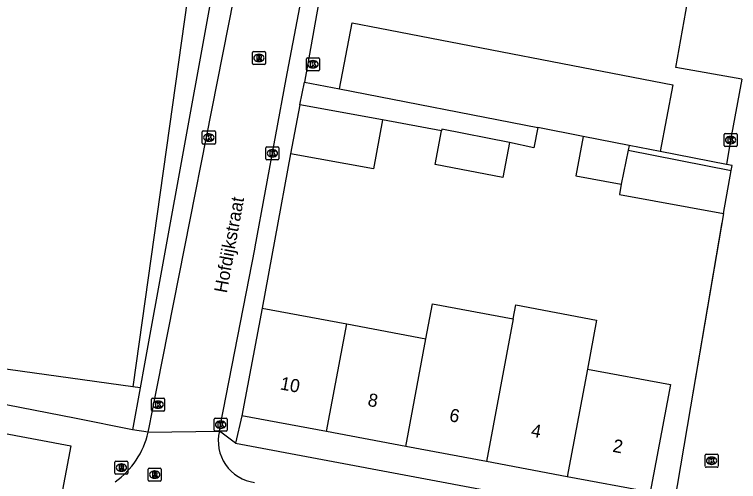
# Model space of a CAD drawing. Extents: x 161402 to 161933, y 381650 to 382313.
# Drawn here: x 161806.7 to 161862.2, y 381952.6 to 381988.4 of the extents above; entities that cross this region are included whole.
import ezdxf

# ---------------------------------------------------------------- set-up
doc = ezdxf.new("R2010")
doc.units = 0
for name, color, linetype in [('IMGEO_Groenvoorziening', 7, 'Continuous'), ('IMGEO_Kolk', 7, 'Continuous'), ('IMGEO_Muur', 7, 'Continuous'), ('IMGEO_Openbare_ruimte_label', 7, 'Continuous'), ('IMGEO_Pand', 7, 'Continuous'), ('IMGEO_Pand_nummerreeks', 7, 'Continuous'), ('IMGEO_Parkeervlak_gesloten', 7, 'Continuous'), ('IMGEO_Rijbaan_lokaal_gesloten', 7, 'Continuous'), ('IMGEO_Rijbaan_lokaal_open', 7, 'Continuous'), ('IMGEO_Rioolput', 7, 'Continuous'), ('IMGEO_Voetpad_open', 7, 'Continuous')]:
    doc.layers.add(name, color=color, linetype=linetype)

msp = doc.modelspace()

# ---------------------------------------------------------------- linework, layer by layer
at = {"layer": 'IMGEO_Groenvoorziening'}
for points in [[(161829.439, 382055.781), (161829.294, 382055.793), (161815.795, 381959.903)], [(161815.795, 381959.903), (161781.596, 381964.647)], [(161816.367, 381959.82), (161815.795, 381959.903)]]:
    msp.add_lwpolyline(points, dxfattribs=at)
at = {"layer": 'IMGEO_Kolk'}
for p, q in [((161829.118, 381984.183), (161829.118, 381985.035)), ((161829.193, 381985.109), (161830.045, 381985.109)), ((161830.119, 381985.035), (161830.119, 381984.183)), ((161829.606, 381984.889), (161829.631, 381984.889)), ((161830.045, 381984.109), (161829.193, 381984.109)), ((161829.629, 381984.329), (161829.604, 381984.329)), ((161821.209, 381979.497), (161822.061, 381979.497)), ((161821.134, 381978.571), (161821.134, 381979.423)), ((161821.622, 381979.277), (161821.647, 381979.277)), ((161822.135, 381979.423), (161822.135, 381978.571)), ((161861.134, 381978.379), (161861.134, 381979.231)), ((161861.209, 381979.305), (161862.061, 381979.305)), ((161861.622, 381979.085), (161861.647, 381979.085)), ((161862.135, 381979.231), (161862.135, 381978.379)), ((161822.061, 381978.497), (161821.209, 381978.497)), ((161821.645, 381978.717), (161821.62, 381978.717)), ((161861.645, 381978.525), (161861.62, 381978.525)), ((161826.008, 381977.362), (161826.008, 381978.214)), ((161826.083, 381978.288), (161826.935, 381978.288)), ((161826.496, 381978.068), (161826.521, 381978.068)), ((161827.009, 381978.214), (161827.009, 381977.362)), ((161862.061, 381978.305), (161861.209, 381978.305)), ((161826.935, 381977.288), (161826.083, 381977.288)), ((161826.519, 381977.508), (161826.494, 381977.508)), ((161817.244, 381958.104), (161817.244, 381958.956)), ((161817.319, 381959.03), (161818.171, 381959.03)), ((161818.245, 381958.956), (161818.245, 381958.104)), ((161817.732, 381958.81), (161817.757, 381958.81)), ((161818.171, 381958.03), (161817.319, 381958.03)), ((161817.755, 381958.25), (161817.73, 381958.25)), ((161822.039, 381956.565), (161822.039, 381957.417)), ((161822.114, 381957.491), (161822.966, 381957.491)), ((161822.527, 381957.271), (161822.552, 381957.271)), ((161823.04, 381957.417), (161823.04, 381956.565)), ((161822.55, 381956.711), (161822.525, 381956.711)), ((161822.966, 381956.491), (161822.114, 381956.491)), ((161859.677, 381953.805), (161859.677, 381954.657)), ((161859.752, 381954.731), (161860.604, 381954.731)), ((161860.165, 381954.511), (161860.19, 381954.511)), ((161860.678, 381954.657), (161860.678, 381953.805)), ((161860.188, 381953.951), (161860.163, 381953.951)), ((161860.604, 381953.731), (161859.752, 381953.731))]:
    msp.add_line(p, q, dxfattribs=at)
for points in [[(161829.118, 381984.183), (161829.118, 381985.035)], [(161829.193, 381985.109), (161830.045, 381985.109)], [(161830.119, 381985.035), (161830.119, 381984.183)], [(161829.439, 381984.809), (161829.562, 381984.809), (161829.562, 381984.658), (161829.692, 381984.809), (161829.856, 381984.809), (161829.71, 381984.658), (161829.863, 381984.409), (161829.711, 381984.409), (161829.626, 381984.573), (161829.562, 381984.506), (161829.562, 381984.409), (161829.439, 381984.409), (161829.439, 381984.809)], [(161830.045, 381984.109), (161829.193, 381984.109)], [(161821.209, 381979.497), (161822.061, 381979.497)], [(161821.134, 381978.571), (161821.134, 381979.423)], [(161821.455, 381979.197), (161821.578, 381979.197), (161821.578, 381979.046), (161821.708, 381979.197), (161821.872, 381979.197), (161821.726, 381979.046), (161821.879, 381978.797), (161821.727, 381978.797), (161821.642, 381978.961), (161821.578, 381978.894), (161821.578, 381978.797), (161821.455, 381978.797), (161821.455, 381979.197)], [(161822.135, 381979.423), (161822.135, 381978.571)], [(161861.134, 381978.379), (161861.134, 381979.231)], [(161861.209, 381979.305), (161862.061, 381979.305)], [(161861.455, 381979.005), (161861.578, 381979.005), (161861.578, 381978.854), (161861.708, 381979.005), (161861.872, 381979.005), (161861.726, 381978.854), (161861.879, 381978.605), (161861.727, 381978.605), (161861.642, 381978.769), (161861.578, 381978.702), (161861.578, 381978.605), (161861.455, 381978.605), (161861.455, 381979.005)], [(161862.135, 381979.231), (161862.135, 381978.379)], [(161822.061, 381978.497), (161821.209, 381978.497)], [(161826.008, 381977.362), (161826.008, 381978.214)], [(161826.083, 381978.288), (161826.935, 381978.288)], [(161826.329, 381977.988), (161826.452, 381977.988), (161826.452, 381977.837), (161826.582, 381977.988), (161826.746, 381977.988), (161826.6, 381977.837), (161826.753, 381977.588), (161826.601, 381977.588), (161826.516, 381977.752), (161826.452, 381977.685), (161826.452, 381977.588), (161826.329, 381977.588), (161826.329, 381977.988)], [(161827.009, 381978.214), (161827.009, 381977.362)], [(161862.061, 381978.305), (161861.209, 381978.305)], [(161826.935, 381977.288), (161826.083, 381977.288)], [(161817.244, 381958.104), (161817.244, 381958.956)], [(161817.319, 381959.03), (161818.171, 381959.03)], [(161818.245, 381958.956), (161818.245, 381958.104)], [(161817.565, 381958.73), (161817.688, 381958.73), (161817.688, 381958.579), (161817.818, 381958.73), (161817.982, 381958.73), (161817.836, 381958.579), (161817.989, 381958.33), (161817.837, 381958.33), (161817.752, 381958.494), (161817.688, 381958.427), (161817.688, 381958.33), (161817.565, 381958.33), (161817.565, 381958.73)], [(161818.171, 381958.03), (161817.319, 381958.03)], [(161822.039, 381956.565), (161822.039, 381957.417)], [(161822.114, 381957.491), (161822.966, 381957.491)], [(161823.04, 381957.417), (161823.04, 381956.565)], [(161822.36, 381957.191), (161822.483, 381957.191), (161822.483, 381957.04), (161822.613, 381957.191), (161822.777, 381957.191), (161822.631, 381957.04), (161822.784, 381956.791), (161822.632, 381956.791), (161822.547, 381956.955), (161822.483, 381956.888), (161822.483, 381956.791), (161822.36, 381956.791), (161822.36, 381957.191)], [(161822.966, 381956.491), (161822.114, 381956.491)], [(161859.677, 381953.805), (161859.677, 381954.657)], [(161859.752, 381954.731), (161860.604, 381954.731)], [(161860.678, 381954.657), (161860.678, 381953.805)], [(161859.998, 381954.431), (161860.121, 381954.431), (161860.121, 381954.28), (161860.251, 381954.431), (161860.415, 381954.431), (161860.269, 381954.28), (161860.422, 381954.031), (161860.27, 381954.031), (161860.185, 381954.195), (161860.121, 381954.128), (161860.121, 381954.031), (161859.998, 381954.031), (161859.998, 381954.431)], [(161860.604, 381953.731), (161859.752, 381953.731)]]:
    msp.add_lwpolyline(points, dxfattribs=at)
for centre, start, end in [((161829.195, 381985.033), 91.552, 178.448), ((161829.195, 381985.033), 91.552, 178.448), ((161830.043, 381985.033), 1.552, 88.448), ((161830.043, 381985.033), 1.552, 88.448), ((161829.195, 381984.185), 181.552, 268.448), ((161829.195, 381984.185), 181.552, 268.448), ((161830.043, 381984.185), 271.552, 358.448), ((161830.043, 381984.185), 271.552, 358.448), ((161821.211, 381979.421), 91.552, 178.448), ((161821.211, 381979.421), 91.552, 178.448), ((161822.059, 381979.421), 1.552, 88.448), ((161822.059, 381979.421), 1.552, 88.448), ((161861.211, 381979.229), 91.552, 178.448), ((161861.211, 381979.229), 91.552, 178.448), ((161862.059, 381979.229), 1.552, 88.448), ((161862.059, 381979.229), 1.552, 88.448), ((161821.211, 381978.573), 181.552, 268.448), ((161821.211, 381978.573), 181.552, 268.448), ((161822.059, 381978.573), 271.552, 358.448), ((161822.059, 381978.573), 271.552, 358.448), ((161861.211, 381978.381), 181.552, 268.448), ((161861.211, 381978.381), 181.552, 268.448), ((161862.059, 381978.381), 271.552, 358.448), ((161862.059, 381978.381), 271.552, 358.448), ((161826.085, 381978.212), 91.552, 178.448), ((161826.085, 381978.212), 91.552, 178.448), ((161826.933, 381978.212), 1.552, 88.448), ((161826.933, 381978.212), 1.552, 88.448), ((161826.085, 381977.364), 181.552, 268.448), ((161826.085, 381977.364), 181.552, 268.448), ((161826.933, 381977.364), 271.552, 358.448), ((161826.933, 381977.364), 271.552, 358.448), ((161817.321, 381958.954), 91.552, 178.448), ((161817.321, 381958.954), 91.552, 178.448), ((161818.169, 381958.954), 1.552, 88.448), ((161818.169, 381958.954), 1.552, 88.448), ((161817.321, 381958.106), 181.552, 268.448), ((161817.321, 381958.106), 181.552, 268.448), ((161818.169, 381958.106), 271.552, 358.448), ((161818.169, 381958.106), 271.552, 358.448), ((161822.116, 381957.415), 91.552, 178.448), ((161822.116, 381957.415), 91.552, 178.448), ((161822.964, 381957.415), 1.552, 88.448), ((161822.964, 381957.415), 1.552, 88.448), ((161822.116, 381956.567), 181.552, 268.448), ((161822.116, 381956.567), 181.552, 268.448), ((161822.964, 381956.567), 271.552, 358.448), ((161822.964, 381956.567), 271.552, 358.448), ((161859.754, 381954.655), 91.552, 178.448), ((161859.754, 381954.655), 91.552, 178.448), ((161860.602, 381954.655), 1.552, 88.448), ((161860.602, 381954.655), 1.552, 88.448), ((161859.754, 381953.807), 181.552, 268.448), ((161859.754, 381953.807), 181.552, 268.448), ((161860.602, 381953.807), 271.552, 358.448), ((161860.602, 381953.807), 271.552, 358.448)]:
    msp.add_arc(centre, 0.0765, start, end, dxfattribs=at)
for centre, major_axis, ratio, start_param, end_param in [((161829.605, 381984.609), (-0.387, 0.002), 0.722429, 4.712389, 7.853982), ((161829.63, 381984.609), (-0.39, 0.002), 0.717154, 1.570796, 4.712389), ((161821.621, 381978.997), (-0.387, 0.002), 0.722429, 4.712389, 7.853982), ((161821.646, 381978.997), (-0.39, 0.002), 0.717154, 1.570796, 4.712389), ((161861.621, 381978.805), (-0.387, 0.002), 0.722429, 4.712389, 7.853982), ((161861.646, 381978.805), (-0.39, 0.002), 0.717154, 1.570796, 4.712389), ((161826.495, 381977.788), (-0.387, 0.002), 0.722429, 4.712389, 7.853982), ((161826.52, 381977.788), (-0.39, 0.002), 0.717154, 1.570796, 4.712389), ((161817.731, 381958.53), (-0.387, 0.002), 0.722429, 4.712389, 7.853982), ((161817.756, 381958.53), (-0.39, 0.002), 0.717154, 1.570796, 4.712389), ((161822.526, 381956.991), (-0.387, 0.002), 0.722429, 4.712389, 7.853982), ((161822.551, 381956.991), (-0.39, 0.002), 0.717154, 1.570796, 4.712389), ((161860.164, 381954.231), (-0.387, 0.002), 0.722429, 4.712389, 7.853982), ((161860.189, 381954.231), (-0.39, 0.002), 0.717154, 1.570796, 4.712389)]:
    msp.add_ellipse(centre, major_axis=major_axis, ratio=ratio, start_param=start_param, end_param=end_param, dxfattribs=at)
at = {"layer": 'IMGEO_Muur'}
for points in [[(161827.883, 381977.756), (161826.684, 381971.203)], [(161860.954, 381972.49), (161858.562, 381958.352)], [(161826.684, 381971.203), (161825.719, 381965.932)]]:
    msp.add_lwpolyline(points, dxfattribs=at)
at = {"layer": 'IMGEO_Pand'}
for points in [[(161828.609, 381981.506), (161827.883, 381977.756)], [(161834.946, 381980.346), (161828.609, 381981.506)], [(161834.946, 381980.346), (161834.257, 381976.588), (161827.883, 381977.756)], [(161844.674, 381978.618), (161844.181, 381975.929), (161838.994, 381976.939), (161839.466, 381979.518)], [(161844.674, 381978.618), (161839.486, 381979.628), (161839.466, 381979.518)], [(161850.336, 381979.079), (161849.782, 381976.057), (161853.257, 381975.42)], [(161853.869, 381978.391), (161850.336, 381979.079)], [(161853.869, 381978.391), (161853.792, 381978.018)], [(161853.792, 381978.018), (161853.257, 381975.42)], [(161853.792, 381978.018), (161861.686, 381976.481)], [(161861.08, 381973.179), (161861.686, 381976.481)], [(161853.257, 381975.42), (161853.114, 381974.64), (161861.08, 381973.179)], [(161838.276, 381963.578), (161838.779, 381966.265), (161844.971, 381965.105)], [(161844.971, 381965.105), (161845.171, 381966.173), (161851.364, 381965.012), (161850.66, 381961.257)], [(161825.719, 381965.932), (161824.173, 381957.682)], [(161825.719, 381965.932), (161832.204, 381964.716)], [(161844.971, 381965.105), (161842.923, 381954.168)], [(161830.659, 381956.466), (161832.204, 381964.716)], [(161832.204, 381964.716), (161838.276, 381963.578)], [(161836.731, 381955.328), (161838.276, 381963.578)], [(161850.66, 381961.257), (161857.027, 381960.063), (161855.481, 381951.814), (161849.115, 381953.007)], [(161850.66, 381961.257), (161849.115, 381953.007)], [(161830.659, 381956.466), (161824.173, 381957.682)], [(161836.731, 381955.328), (161830.659, 381956.466)], [(161842.923, 381954.168), (161836.731, 381955.328)], [(161849.115, 381953.007), (161842.923, 381954.168)]]:
    msp.add_lwpolyline(points, dxfattribs=at)
at = {"layer": 'IMGEO_Parkeervlak_gesloten'}
for points in [[(161850.336, 381979.079), (161846.863, 381979.756)], [(161856.229, 381977.931), (161853.869, 381978.391)]]:
    msp.add_lwpolyline(points, dxfattribs=at)
at = {"layer": 'IMGEO_Rijbaan_lokaal_gesloten'}
for points in [[(161862.491, 381983.458), (161857.448, 381984.357), (161864.341, 382023.003)], [(161830.987, 381994.574), (161828.968, 381983.243)], [(161831.646, 381982.721), (161832.631, 381987.778), (161834.75, 381987.369), (161857.213, 381983.04), (161856.229, 381977.931)], [(161862.491, 381983.458), (161861.636, 381978.805), (161861.321, 381976.94)], [(161828.968, 381983.243), (161831.646, 381982.721)], [(161861.321, 381976.94), (161856.229, 381977.931)]]:
    msp.add_lwpolyline(points, dxfattribs=at)
at = {"layer": 'IMGEO_Rijbaan_lokaal_open'}
for points in [[(161822.45, 381956.505), (161822.54, 381956.991), (161825.164, 381970.44), (161825.196, 381970.616), (161827.554, 381983.498), (161830.695, 382000), (161833.899, 382016.966), (161836.784, 382033.46), (161839.275, 382047.946), (161841.729, 382061.924), (161844.797, 382079.199), (161847.522, 382094.137), (161855.583, 382102.928), (161859.869, 382107.508)], [(161816.977, 381956.412), (161817.094, 381956.896), (161817.254, 381957.834), (161824.386, 381993.913), (161825.157, 381998.089), (161825.499, 382000), (161827.39, 382010.57), (161829.195, 382020.232), (161830.73, 382029.273), (161834.543, 382050.384), (161834.774, 382051.699)], [(161832.505, 382048.322), (161822.827, 381995.34), (161816.701, 381961.668), (161816.367, 381959.82)], [(161828.609, 381981.506), (161828.968, 381983.243)], [(161827.883, 381977.756), (161826.684, 381971.203), (161825.719, 381965.932)], [(161861.686, 381976.481), (161861.755, 381976.855), (161861.321, 381976.94)], [(161861.08, 381973.179), (161858.562, 381958.352), (161857.033, 381949.323)], [(161816.367, 381959.82), (161815.783, 381956.589)], [(161824.173, 381957.682), (161823.681, 381955.575)], [(161816.977, 381956.412), (161815.783, 381956.589)], [(161816.977, 381956.412), (161822.45, 381956.505)], [(161823.681, 381955.575), (161822.45, 381956.505)]]:
    msp.add_lwpolyline(points, dxfattribs=at)
for centre, radius, start, end in [((161810.822, 381957.769), 6.303, 305.142, 347.5685), ((161825.556, 381955.744), 3.198, 166.2409, 262.5929)]:
    msp.add_arc(centre, radius, start, end, dxfattribs=at)
at = {"layer": 'IMGEO_Rioolput'}
for p, q in [((161825.047, 381985.592), (161825.899, 381985.592)), ((161824.972, 381984.666), (161824.972, 381985.518)), ((161825.46, 381985.372), (161825.485, 381985.372)), ((161825.973, 381985.518), (161825.973, 381984.666)), ((161825.899, 381984.592), (161825.047, 381984.592)), ((161825.483, 381984.812), (161825.458, 381984.812)), ((161814.43, 381953.279), (161814.43, 381954.131)), ((161814.505, 381954.205), (161815.357, 381954.205)), ((161814.918, 381953.985), (161814.943, 381953.985)), ((161815.431, 381954.131), (161815.431, 381953.279)), ((161814.941, 381953.425), (161814.916, 381953.425)), ((161816.986, 381952.744), (161816.986, 381953.596)), ((161817.061, 381953.67), (161817.913, 381953.67)), ((161817.474, 381953.45), (161817.499, 381953.45)), ((161817.987, 381953.596), (161817.987, 381952.744)), ((161815.357, 381953.205), (161814.505, 381953.205)), ((161817.497, 381952.89), (161817.472, 381952.89)), ((161817.913, 381952.67), (161817.061, 381952.67))]:
    msp.add_line(p, q, dxfattribs=at)
for points in [[(161825.047, 381985.592), (161825.899, 381985.592)], [(161824.972, 381984.666), (161824.972, 381985.518)], [(161825.561, 381985.29), (161825.309, 381985.292), (161825.309, 381984.892)], [(161825.309, 381984.892), (161825.433, 381984.892), (161825.433, 381985.054), (161825.444, 381985.054)], [(161825.487, 381985.211), (161825.433, 381985.211), (161825.433, 381985.13)], [(161825.433, 381985.13), (161825.485, 381985.13)], [(161825.491, 381985.025), (161825.562, 381984.892), (161825.702, 381984.892), (161825.637, 381985.018)], [(161825.973, 381985.518), (161825.973, 381984.666)], [(161825.899, 381984.592), (161825.047, 381984.592)], [(161814.43, 381953.279), (161814.43, 381954.131)], [(161814.505, 381954.205), (161815.357, 381954.205)], [(161815.019, 381953.903), (161814.767, 381953.905), (161814.767, 381953.505)], [(161815.431, 381954.131), (161815.431, 381953.279)], [(161814.767, 381953.505), (161814.891, 381953.505), (161814.891, 381953.667), (161814.902, 381953.667)], [(161814.945, 381953.824), (161814.891, 381953.824), (161814.891, 381953.743)], [(161814.891, 381953.743), (161814.943, 381953.743)], [(161814.949, 381953.638), (161815.02, 381953.505), (161815.16, 381953.505), (161815.095, 381953.631)], [(161816.986, 381952.744), (161816.986, 381953.596)], [(161817.061, 381953.67), (161817.913, 381953.67)], [(161817.575, 381953.368), (161817.323, 381953.37), (161817.323, 381952.97)], [(161817.987, 381953.596), (161817.987, 381952.744)], [(161815.357, 381953.205), (161814.505, 381953.205)], [(161817.323, 381952.97), (161817.447, 381952.97), (161817.447, 381953.132), (161817.458, 381953.132)], [(161817.501, 381953.289), (161817.447, 381953.289), (161817.447, 381953.208)], [(161817.447, 381953.208), (161817.499, 381953.208)], [(161817.505, 381953.103), (161817.576, 381952.97), (161817.716, 381952.97), (161817.651, 381953.096)], [(161817.913, 381952.67), (161817.061, 381952.67)]]:
    msp.add_lwpolyline(points, dxfattribs=at)
for centre, radius, start, end in [((161825.049, 381985.516), 0.0765, 91.552, 178.448), ((161825.049, 381985.516), 0.0765, 91.552, 178.448), ((161825.897, 381985.516), 0.0765, 1.552, 88.448), ((161825.897, 381985.516), 0.0765, 1.552, 88.448), ((161825.443, 381985.001), 0.0533, 26.0293, 88.6989), ((161825.469, 381985.319), 0.19, 274.7715, 282.9687), ((161825.493, 381985.115), 0.0964, 77.0061, 93.1865), ((161825.507, 381985.172), 0.0378, 276.6634, 79.6772), ((161825.56, 381985.18), 0.109, 350.3612, 89.416), ((161825.558, 381985.18), 0.112, 277.5842, 350.9817), ((161825.542, 381984.965), 0.108, 29.5134, 73.7905), ((161825.049, 381984.668), 0.0765, 181.552, 268.448), ((161825.049, 381984.668), 0.0765, 181.552, 268.448), ((161825.897, 381984.668), 0.0765, 271.552, 358.448), ((161825.897, 381984.668), 0.0765, 271.552, 358.448), ((161814.507, 381954.129), 0.0765, 91.552, 178.448), ((161814.507, 381954.129), 0.0765, 91.552, 178.448), ((161815.018, 381953.793), 0.109, 350.3612, 89.416), ((161815.355, 381954.129), 0.0765, 1.552, 88.448), ((161815.355, 381954.129), 0.0765, 1.552, 88.448), ((161814.901, 381953.614), 0.0533, 26.0293, 88.6989), ((161814.927, 381953.932), 0.19, 274.7715, 282.9687), ((161814.951, 381953.728), 0.0964, 77.0061, 93.1865), ((161814.965, 381953.785), 0.0378, 276.6634, 79.6772), ((161815.016, 381953.793), 0.112, 277.5842, 350.9817), ((161815, 381953.578), 0.108, 29.5134, 73.7905), ((161817.063, 381953.594), 0.0765, 91.552, 178.448), ((161817.063, 381953.594), 0.0765, 91.552, 178.448), ((161817.574, 381953.258), 0.109, 350.3612, 89.416), ((161817.911, 381953.594), 0.0765, 1.552, 88.448), ((161817.911, 381953.594), 0.0765, 1.552, 88.448), ((161814.507, 381953.281), 0.0765, 181.552, 268.448), ((161814.507, 381953.281), 0.0765, 181.552, 268.448), ((161815.355, 381953.281), 0.0765, 271.552, 358.448), ((161815.355, 381953.281), 0.0765, 271.552, 358.448), ((161817.457, 381953.079), 0.0533, 26.0293, 88.6989), ((161817.483, 381953.397), 0.19, 274.7715, 282.9687), ((161817.507, 381953.193), 0.0964, 77.0061, 93.1865), ((161817.521, 381953.25), 0.0378, 276.6634, 79.6772), ((161817.572, 381953.258), 0.112, 277.5842, 350.9817), ((161817.556, 381953.043), 0.108, 29.5134, 73.7905), ((161817.063, 381952.746), 0.0765, 181.552, 268.448), ((161817.063, 381952.746), 0.0765, 181.552, 268.448), ((161817.911, 381952.746), 0.0765, 271.552, 358.448), ((161817.911, 381952.746), 0.0765, 271.552, 358.448)]:
    msp.add_arc(centre, radius, start, end, dxfattribs=at)
for centre, major_axis, ratio, start_param, end_param in [((161825.459, 381985.092), (-0.387, 0.002), 0.722429, 4.712389, 7.853982), ((161825.484, 381985.092), (-0.39, 0.002), 0.717154, 1.570796, 4.712389), ((161814.917, 381953.705), (-0.387, 0.002), 0.722429, 4.712389, 7.853982), ((161814.942, 381953.705), (-0.39, 0.002), 0.717154, 1.570796, 4.712389), ((161817.473, 381953.17), (-0.387, 0.002), 0.722429, 4.712389, 7.853982), ((161817.498, 381953.17), (-0.39, 0.002), 0.717154, 1.570796, 4.712389)]:
    msp.add_ellipse(centre, major_axis=major_axis, ratio=ratio, start_param=start_param, end_param=end_param, dxfattribs=at)
at = {"layer": 'IMGEO_Voetpad_open'}
for points in [[(161831.646, 381982.721), (161846.863, 381979.756)], [(161839.466, 381979.518), (161834.946, 381980.346)], [(161846.863, 381979.756), (161846.563, 381978.219), (161844.674, 381978.618)], [(161815.783, 381956.589), (161811.468, 381957.46), (161794.405, 381960.779), (161794.464, 381961.223), (161793.08, 381961.474), (161793.007, 381961.051), (161785.921, 381962.429)], [(161784.276, 381957.939), (161785.503, 381960.377), (161795.166, 381958.474), (161794.855, 381956.97), (161793.688, 381954.764), (161795.715, 381953.673), (161796.806, 381955.759), (161796.395, 381956.022), (161796.644, 381956.673), (161796.895, 381958.043), (161811.053, 381955.38), (161810.228, 381951.049)], [(161823.681, 381955.575), (161857.033, 381949.323)]]:
    msp.add_lwpolyline(points, dxfattribs=at)

# ---------------------------------------------------------------- texts
at = {"layer": 'IMGEO_Openbare_ruimte_label'}
msp.add_text('Hofdijkstraat', height=1, rotation=79.6337, dxfattribs=at).set_placement((161823.01, 381967.036))
at = {"layer": 'IMGEO_Pand_nummerreeks'}
for s, p in [('10', (161827.048, 381959.707)), ('8', (161833.764, 381958.448)), ('6', (161840.021, 381957.275)), ('4', (161846.283, 381956.102)), ('2', (161852.542, 381954.928))]:
    msp.add_text(s, height=1, rotation=349.3843, dxfattribs=at).set_placement(p)

doc.saveas('drawing.dxf')
